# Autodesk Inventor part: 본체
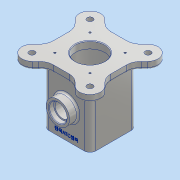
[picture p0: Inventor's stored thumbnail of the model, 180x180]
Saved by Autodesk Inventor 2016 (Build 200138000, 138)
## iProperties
Created: 2019-11
Part Number: 본체
Material: 알루미늄 6061
Document SubType Name: Modeling
Designer: user
Density: 2.7 g/cm^3
Appearance: 알루미늄 - 평지
Mass: 1073.02 g
Surface Area: 877.335 cm^2
Volume: 397.416 cm^3
Author: user
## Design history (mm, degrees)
sketch "스케치1"
  geometry: L1 (49, -49)-(-49, -49); L2 (-49, -49)-(-49, 49); L3 (-49, 49)-(49, 49); L4 (49, 49)-(49, -49); L5 (49, -49)-(-49, 49); L6 (-49, -49)-(49, 49); L7 (-49, -49)-(49, 49); L8 (-61.728, -36.272)-(36.272, 61.728); L9 (61.728, 36.272)-(-36.272, -61.728); L10 (-49, 49)-(49, -49); L11 (-36.272, 61.728)-(61.728, -36.272); L12 (36.272, -61.728)-(-61.728, 36.272); A1 r 18 centre (-49, -49) between (-61.728, -36.272) and (-36.272, -61.728); A2 r 18 centre (49, 49) between (61.728, 36.272) and (36.272, 61.728); A3 r 18 centre (-49, 49) between (-36.272, 61.728) and (-61.728, 36.272); A4 r 18 centre (49, -49) between (36.272, -61.728) and (61.728, -36.272); 3 further points
  constraints: 28 end point, 8 point on circle, 8 tangent, 4 centre point, 4 midpoint, 4 parallel, 1 horizontal, 1 perpendicular
  dimensions: "d0" = 98 distance of L2.end L3.end; "d1" = 98 distance of L3.end L1.start; "d2" = 36 distance between parallel lines of L8 L9; "d3" = 36 distance between parallel lines of L12 L11
extrude "돌출1" new body sketch "스케치1" distance "d4" = 12; taper "d5" = 0 deg
sketch "스케치3" dims "d6" = 140
  geometry: L1 (-61.728, 36.272)-(-49, 23.544) reference; C1 r 9 at (-49.497, 49.497); 2 further points
  constraints: 1 centre point, 1 coincident, 3 other
  dimensions: "d7" = 18 diameter of C1; "d8" = 18 distance from line of C1.centre L1
hole "구멍1" sketch "스케치3" at (-49.497, 49.497) diameter "d9" = 10; stored, may be unused: countersink angle "d13" = 90 deg, drill point angle "d15" = 118 deg; dims "d10" = 6, "d11" = 18, "d12" = 4, "d14" = 8
sketch "스케치5"
  geometry: C1 r 25 at (0, 0); 1 further point
  constraints: 1 centre point, 1 coincident
  dimensions: "d25" = 50 diameter of C1
extrude "돌출2" cut sketch "스케치5" distance "d26" = 12; taper "d27" = 0 deg
sketch "스케치6"
  geometry: L1 (-30, -30)-(30, -30); L2 (30, -30)-(30, 30); L3 (30, 30)-(-30, 30); L4 (-30, 30)-(-30, -30); L5 (-30, -30)-(30, 30); L6 (30, -30)-(-30, 30); 2 further points
  constraints: 12 end point, 2 midpoint, 2 parallel, 1 coincident, 1 horizontal, 1 perpendicular
  dimensions: "d31" = 60 distance of L1.end L2.end; "d32" = 60 distance of L1.start L1.end
hole "구멍3" sketch "스케치6" at (30, 30) diameter "d33" = 3.242; stored, may be unused: countersink angle "d37" = 90 deg, drill point angle "d39" = 118 deg; dims "d34" = 8, "d35" = 18, "d36" = 5, "d38" = 10
sketch "스케치7"
  geometry: L1 (40, -40)-(-40, -40); L2 (-40, -40)-(-40, 40); L3 (-40, 40)-(40, 40); L4 (40, 40)-(40, -40); L5 (40, -40)-(-40, 40); L6 (-40, -40)-(40, 40); 1 further point
  constraints: 12 end point, 2 midpoint, 2 parallel, 1 horizontal, 1 perpendicular
  dimensions: "d43" = 80 distance of L1.start L1.end; "d44" = 80 distance of L1.end L2.end
extrude "돌출3" join sketch "스케치7" distance "d45" = 98; taper "d46" = 0 deg
sketch "스케치8"
  geometry: C1 r 25 at (0, 0); 1 further point
  constraints: 1 centre point, 1 coincident
  dimensions: "d47" = 50 diameter of C1
extrude "돌출4" cut sketch "스케치8" distance "d48" = 110; taper "d49" = 0 deg
sketch "스케치9"
  geometry: C1 r 35 at (0, 0); 1 further point
  constraints: 1 centre point, 1 coincident
  dimensions: "d50" = 70 diameter of C1
extrude "돌출5" cut sketch "스케치9" distance "d51" = 86; taper "d52" = 0 deg
node "작업 평면1"
sketch "스케치11"
  geometry: L1 (23.544, 0)-(36.272, 0) reference; C1 r 20 at (0, -49); 1 further point
  constraints: 1 centre point, 1 vertical alignment
  dimensions: "d54" = 40 diameter of C1; "d55" = 49 distance from line of L1 C1.centre
extrude "돌출6" join sketch "스케치11" stored distance "d56" = 86; taper "d57" = 0 deg
sketch "스케치12"
  geometry: C1 r 15 at (0, 0); 1 further point
  constraints: 1 centre point
  dimensions: "d58" = 30 diameter of C1
extrude "돌출7" cut sketch "스케치12" distance "d59" = 8; taper "d60" = 0 deg
sketch "스케치13"
  geometry: L1 (-23.544, 49)-(-36.272, 49) reference; C1 r 12.5 at (0, 0); 1 further point
  constraints: 1 centre point, 1 vertical alignment
  dimensions: "d61" = 25 diameter of C1; "d62" = 49 distance from line of L1 C1.centre
extrude "돌출8" cut sketch "스케치13" distance "d63" = 40; taper "d64" = 0 deg
sketch "스케치14"
  geometry: C1 r 1.621 at (30, -30) reference; 2 further points
  constraints: 1 coincident
hole "구멍4" sketch "스케치14" at (30, -30) diameter "d65" = 3.242; stored, may be unused: countersink angle "d69" = 90 deg, drill point angle "d71" = 118 deg; dims "d66" = 8, "d67" = 18, "d68" = 5, "d70" = 10
fillet "모깎기1" dims "d75" = 25
chamfer "모따기1" distance "d76" = 1; stored, may be unused: second distance "d77" = 2, angle "d78" = 45 deg
fillet "모깎기2" dims "d79" = 3
fillet "모깎기3" dims "d80" = 10
fillet "모깎기4" dims "d81" = 3
sketch "스케치15" dims "d0" = 98, "d1" = 98, "d2" = 36, "d3" = 36
  geometry: L1 (60, 0)-(0, 0) reference; C1 r 20 at (30, 49) reference; 2 further points
  constraints: 1 vertical alignment, 1 other
  dimensions: "d82" = 10 distance from line of L1 point (30, 10)
feature "엠보싱1" sketch "스케치15" dims "d0" = 98, "d1" = 98, "d2" = 36, "d3" = 36, "d83" = 0.5, "d84" = 0
fillet "모깎기5" dims "d85" = 3
node "솔리드1"
pattern_circular "원형 패턴1" dims angle "d29" = 360 deg
pattern_circular "원형 패턴2" dims angle "d41" = 360 deg
pattern_circular "원형 패턴3" dims angle "d73" = 360 deg
other parameters: "d53" = -55
